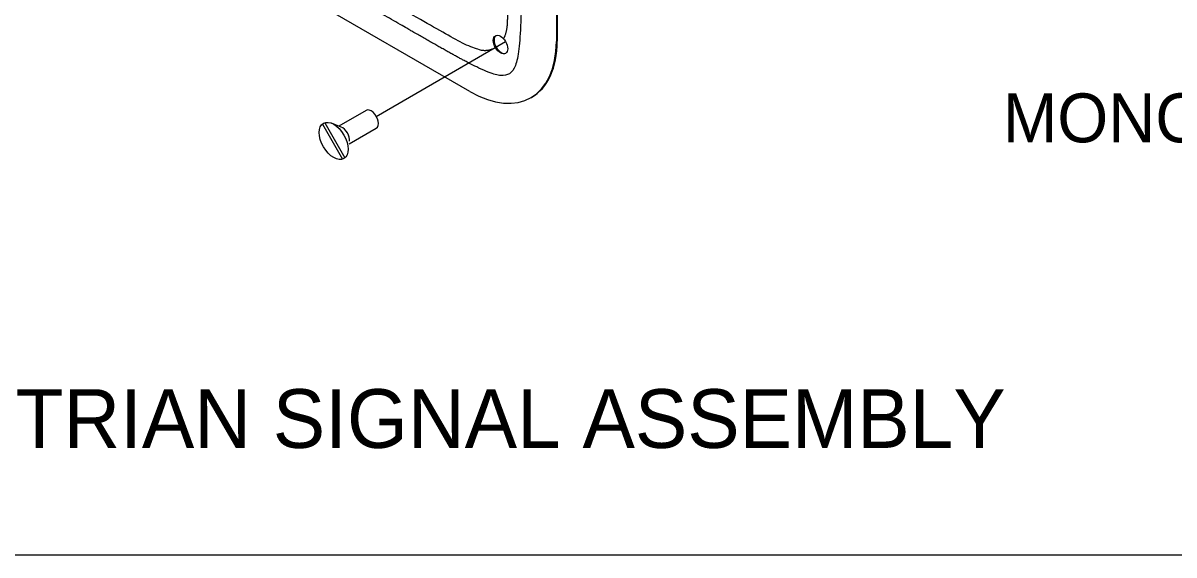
# Model space of a CAD drawing. Extents: x 2815109 to 2818234, y 992846 to 994883.
# Drawn here: x 2816189 to 2816761, y 992846 to 993110 of the extents above; entities that cross this region are included whole.
import ezdxf

# ---------------------------------------------------------------- set-up
doc = ezdxf.new("R2010")
doc.units = 0
for name, color, linetype in [('Common-Notes', 7, 'Continuous'), ('Default', 7, 'Continuous'), ('Draft_Named_Boundary', 7, 'Continuous'), ('Level 16', 7, 'Continuous'), ('Level 40', 7, 'Continuous'), ('Level 41', 7, 'Continuous')]:
    doc.layers.add(name, color=color, linetype=linetype)

msp = doc.modelspace()

# ---------------------------------------------------------------- linework, layer by layer
at = {"layer": 'Draft_Named_Boundary'}
msp.add_lwpolyline([(2815109.48, 992845.97), (2818234.48, 992845.97), (2818234.48, 994883.47), (2815109.48, 994883.47)], close=True, dxfattribs=at)
at = {"layer": 'Level 16'}
for p in [(2816364.29, 993063.86), (2816395.42, 993081.84)]:
    msp.add_line(p, (2816428.54, 993100.96), dxfattribs=at)
at = {"layer": 'Level 40'}
for p, q in [((2816453.78, 993515.02), (2816453.78, 993101)), ((2816454.14, 993515.22), (2816454.14, 993101.21)), ((2816410.82, 993076.2), (2816239, 993175.41))]:
    msp.add_line(p, q, dxfattribs=at)
for centre, major_axis, start_param, end_param in [((2816426.01, 993099.5), (-2.53, 4.38), 0, 6.283182), ((2816426.37, 993099.71), (-2.53, 4.38), 0.07077, 3.070823), ((2816410.82, 993125.81), (30.38, -52.61), 5.497787, 7.068583), ((2816426.01, 993099.5), (-2.53, 4.38), 4.712384, 4.712388), ((2816411.18, 993126.01), (30.38, -52.61), 6.277293, 7.068583)]:
    msp.add_ellipse(centre, major_axis=major_axis, ratio=0.57735, start_param=start_param, end_param=end_param, dxfattribs=at)
for points in [[(2816408.01, 993571.26), (2816322.1, 993620.87), (2816236.19, 993670.47), (2816207.55, 993687), (2816207.55, 993653.93), (2816207.55, 993446.93), (2816207.55, 993239.92), (2816207.55, 993206.85), (2816236.19, 993190.32), (2816322.1, 993140.72), (2816408.01, 993091.11), (2816436.65, 993074.58), (2816436.65, 993107.65), (2816436.65, 993314.66), (2816436.65, 993521.66), (2816436.65, 993554.73), (2816408.01, 993571.26)], [(2816214.71, 993310.36), (2816322.1, 993248.35), (2816429.49, 993186.35), (2816429.49, 993149.07), (2816429.49, 993111.78), (2816429.49, 993106.26), (2816427.47, 993102.44)], [(2816423.48, 993098.04), (2816417.14, 993094.11), (2816408.01, 993099.38), (2816322.1, 993148.98), (2816236.19, 993198.59), (2816214.71, 993210.99), (2816214.71, 993235.79), (2816214.71, 993273.07), (2816214.71, 993310.36)]]:
    msp.add_open_spline(points, degree=4, dxfattribs=at)
at = {"layer": 'Level 41'}
for p, q in [((2816359.22, 993066.79), (2816345.73, 993058.99)), ((2816337.53, 993060.03), (2816347.59, 993042.61)), ((2816338.7, 993060.7), (2816348.75, 993043.28)), ((2816346.88, 993058.54), (2816342.03, 993060.46)), ((2816350.79, 993050.23), (2816364.29, 993058.02))]:
    msp.add_line(p, q, dxfattribs=at)
for centre, start_param, end_param in [((2816361.76, 993062.4), 6.28318, 9.424778), ((2816361.76, 993062.4), 3.141593, 3.141605), ((2816347.44, 993054.13), 0.630137, 2.511455)]:
    msp.add_ellipse(centre, major_axis=(2.53, -4.38), ratio=0.57735, start_param=start_param, end_param=end_param, dxfattribs=at)
msp.add_ellipse((2816343.14, 993051.65), major_axis=(-5.06, 8.77), ratio=0.57735, dxfattribs=at)

# ---------------------------------------------------------------- texts
at = {"layer": 'Common-Notes'}
msp.add_text('ACCESSIBLE PEDESTRIAN SIGNAL ASSEMBLY', height=29.16, dxfattribs=at).set_placement((2815797.16, 992899.16))
at = {"layer": 'Default'}
msp.add_text('MONOLITHIC INSTALLATION', height=24.3, dxfattribs=at).set_placement((2816675.53, 993050.94))

doc.saveas('drawing.dxf')
